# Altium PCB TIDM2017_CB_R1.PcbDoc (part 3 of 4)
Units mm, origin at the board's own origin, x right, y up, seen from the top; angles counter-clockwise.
Board outline 120 x 77 mm, 4 copper layers (Top Layer, Layer 1, Layer 2, Bottom Layer), stack 1.856 mm thick; 246 components, 167 nets, 1255 pads, 326 vias.
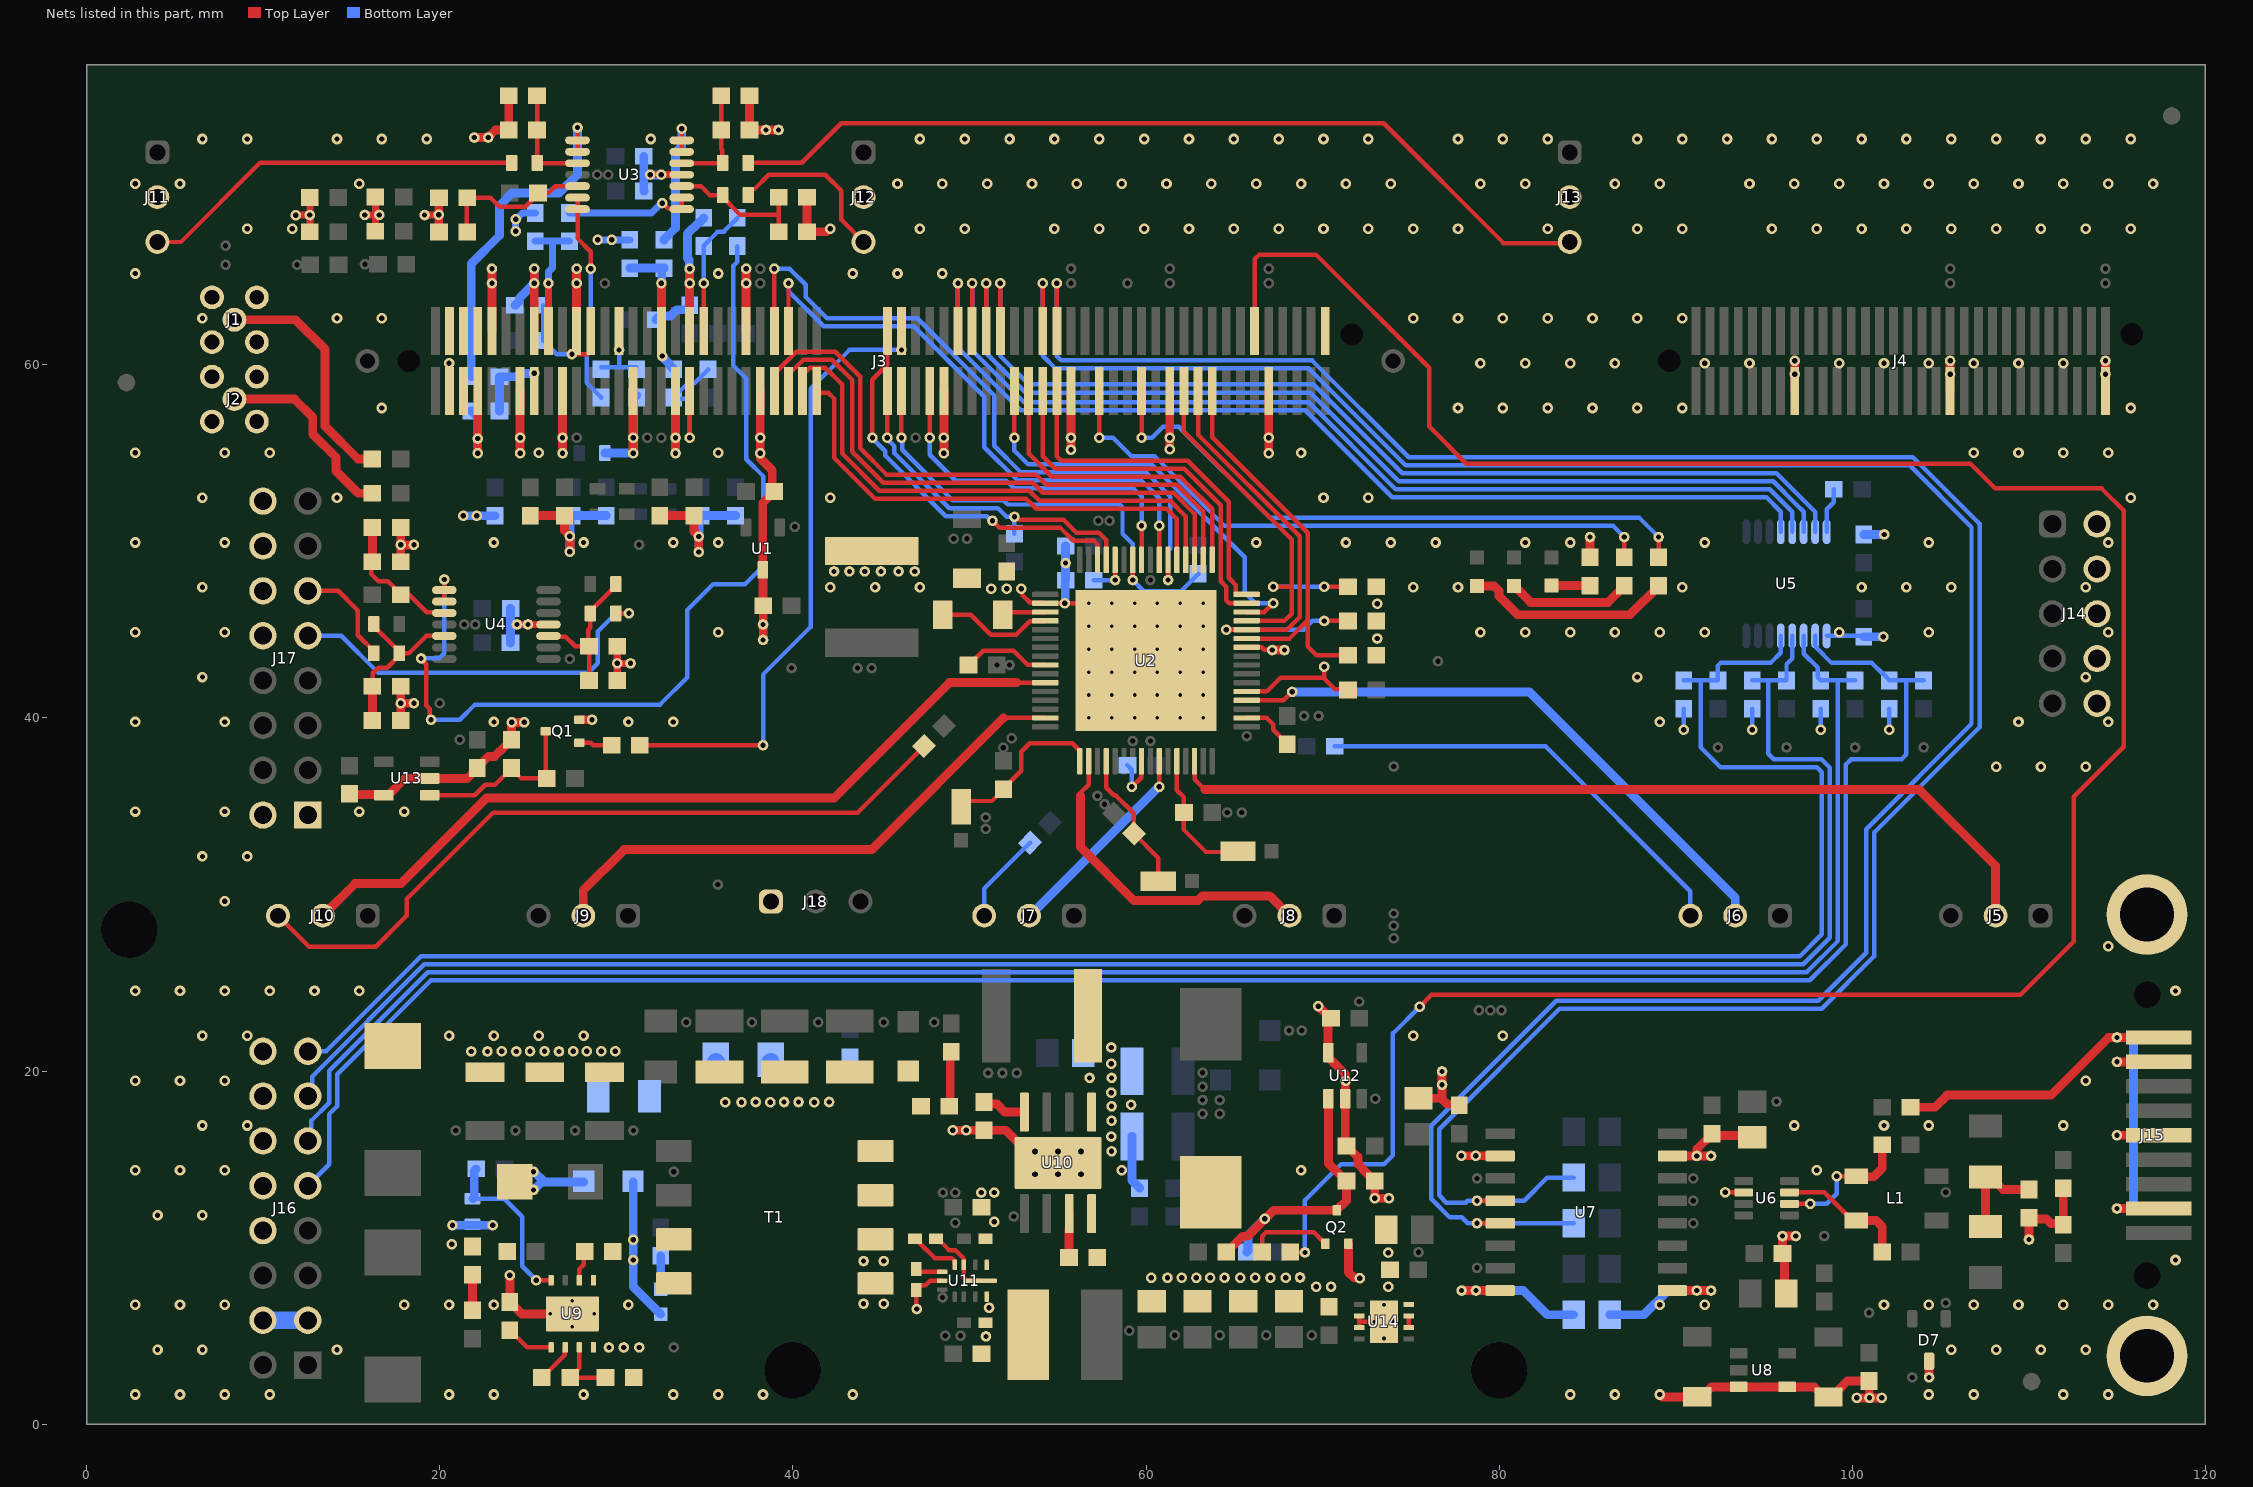
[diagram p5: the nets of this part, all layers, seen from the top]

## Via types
v1: diameter 0.6, hole 0.3, Top Layer to Bottom Layer, 276 vias
v2: diameter 0.5, hole 0.2, Top Layer to Bottom Layer, 40 vias
v3: diameter 0.63, hole 0.33, Top Layer to Bottom Layer, tented both sides, 6 vias
v4: diameter 0.5, hole 0.2, Top Layer to Bottom Layer, tented both sides, 4 vias

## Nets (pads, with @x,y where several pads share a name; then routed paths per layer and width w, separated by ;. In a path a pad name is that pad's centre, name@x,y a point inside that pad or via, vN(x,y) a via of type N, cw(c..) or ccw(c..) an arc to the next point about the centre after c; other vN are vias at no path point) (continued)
DRV_DRVOFF: J3.59 pad.2@46.15,55.875 pad.2@59.25,47.811 R11.1 U2.10 | length 27.1
  Top Layer w0.254: pad.2@46.15,55.875 J3.59@46.15,58.519 ; pad.2@59.25,47.811 U2.10@59.25,48.95
  Bottom Layer w0.254: pad.2@46.15,55.875 46.185,55.84 46.185,55.194 49.039,52.34 51.915,52.34 52.165,52.091 58.52,52.091 58.669,51.942 58.669,50.437 59.25,49.856 pad.2@59.25,47.811 59.877,47.184 61.986,47.184 62.95,48.148 R11.1@62.95,48.173
DRV_nASCIN: J3.63 pad.2@47.75,55.875 pad.2@59.75,50.884 U2.9 | length 20.2
  Top Layer w0.254: pad.2@47.75,55.875 J3.63@47.75,58.519 ; U2.9@59.75,48.95 pad.2@59.75,50.884
  Bottom Layer w0.254: pad.2@47.75,55.875 47.75,54.913 49.22,53.443 52.097,53.443 52.541,52.999 59.296,52.999 59.75,52.545 pad.2@59.75,50.884
DRV_nFLT1: J3.57 pad.2@45.35,55.875 pad.2@52.55,51.389 R21.2 U2.13 | length 19.8
  Top Layer w0.254: pad.2@45.35,55.875 J3.57@45.35,58.519 ; pad.2@52.55,51.389 52.644,51.389 52.817,51.216 55.341,51.216 56.059,50.498 57.333,50.498 57.75,50.081 U2.13@57.75,48.95
  Bottom Layer w0.254: pad.2@45.35,55.875 45.35,55.781 45.731,55.4 45.731,55.006 48.851,51.886 51.613,51.886 52.103,51.397 pad.2@52.542,51.397 ; R21.2@52.55,50.442 pad.2@52.55,51.389
DRV_nFLT2: pad.2@70.091,42.905 R22.2 U2.53 | length 7
  Top Layer w0.254: U2.53@65.7,41.5 66.845,41.5 67.62,42.275 70.054,42.275 ; pad.2@70.091,42.905 70.091,42.312 70.054,42.275 ; R22.2@71.439,41.587 71.403,41.622 70.706,41.622 70.054,42.275
DRV_nSLEEP: J3.58 pad.2@44.502,55.875 pad.2@51.305,51.17 U2.14 | length 22.7
  Top Layer w0.254: pad.2@44.502,55.875 44.502,59.156 45.35,60.004 J3.58@45.35,61.919 ; pad.2@51.305,51.17 51.712,50.762 55.153,50.762 55.871,50.044 57.058,50.044 57.25,49.852 U2.14@57.25,48.95
  Bottom Layer w0.254: pad.2@44.502,55.875 44.502,55.836 45.09,55.248 ; 45.091,55.248 45.24,55.099 45.24,54.855 48.663,51.432 50.983,51.432 51.246,51.17 pad.2@51.305,51.17
DRV_PHCA: J3.103 R14.2 U2.59 | length 23.6
  Top Layer w0.254: J3.103@63.75,58.55 63.75,55.892 69.156,50.486 69.156,45.528 ; U2.59@65.7,44.5 68.129,44.5 69.156,45.528 ; R14.2@71.091,43.899 R14.2@71.439,43.551 69.655,43.551 69.156,44.05 69.156,45.528
DRV_PHCB: J3.101 pad.2@64.55,45 pad.2@70.091,45.493 R19.2 U2.60 | length 26.8
  Top Layer w0.254: J3.101@62.95,58.55 62.95,56.05 68.702,50.298 68.702,45.716 67.987,45 U2.60@65.7,45 pad.2@64.55,45 ; pad.2@70.091,45.493 R19.2@71.439,45.493 R19.2@71.45,45.493
  Bottom Layer w0.254: pad.2@64.55,45 68.928,45 69.421,45.493 pad.2@70.091,45.493
DRV_PHCC: J3.99 pad.2@67.202,47.434 pad.2@70.091,47.434 R20.2 U2.61 | length 23.3
  Top Layer w0.254: J3.99@62.222,58.478 62.15,58.55 62.15,56.208 68.248,50.11 68.248,47.5 ; U2.61@65.7,45.5 67.845,45.5 68.248,45.904 68.248,47.5 ; pad.2@67.202,47.434 68.183,47.434 68.248,47.5 ; pad.2@70.091,47.434 R20.2@71.439,47.434
  Bottom Layer w0.254: pad.2@67.202,47.434 pad.2@70.091,47.434
DRV_PWM_AH: J3.49 U2.2 | length 34.6
  Top Layer w0.254: J3.49@38.95,58.55 38.95,59.504 40.196,60.75 42.392,60.75 43.813,59.329 43.813,55.269 45.296,53.785 53.767,53.785 54.347,53.205 54.48,53.205 ; 54.48,53.205 61.744,53.205 63.25,51.699 U2.2@63.25,48.95
DRV_PWM_AL: J3.51 U2.3 | length 32.9
  Top Layer w0.254: J3.51@39.75,58.55 39.75,59.45 40.596,60.296 42.204,60.296 43.359,59.141 43.359,55.08 45.108,53.331 53.579,53.331 54.159,52.751 61.555,52.751 62.75,51.556 U2.3@62.75,48.95
DRV_PWM_BH: J3.53 U2.4 | length 31
  Top Layer w0.254: J3.53@40.55,58.55 40.55,59.426 40.966,59.842 41.84,59.842 42.785,58.897 42.785,54.986 44.893,52.877 53.391,52.877 53.971,52.297 61.367,52.297 62.25,51.414 U2.4@62.25,48.95
DRV_PWM_BL: J3.55 U2.5 | length 27.7
  Top Layer w0.254: J3.55@41.35,58.519 41.451,58.418 42.003,58.418 42.331,58.09 42.331,54.746 44.654,52.423 53.203,52.423 53.584,52.042 53.783,51.843 61.179,51.843 61.75,51.272 U2.5@61.75,48.95
DRV_PWM_CH: J3.50 pad.2@38.95,65.45 pad.2@61.25,47.811 U2.6 | length 39.3
  Top Layer w0.254: J3.50@38.95,61.95 pad.2@38.95,65.45 ; pad.2@61.25,47.773 pad.2@61.25,47.811 U2.6@61.25,48.95
  Bottom Layer w0.254: pad.2@38.95,65.45 39.812,65.45 40.721,64.541 40.721,63.847 41.932,62.636 47.039,62.636 51.412,58.263 51.412,55.412 52.917,53.907 60.01,53.907 61.377,52.539 61.377,49.588 61.25,49.461 pad.2@61.25,47.811
DRV_PWM_CL: J3.52 pad.2@39.75,64.625 pad.2@60.75,50.884 U2.7 | length 34.1
  Top Layer w0.254: J3.52@39.75,61.95 pad.2@39.75,64.625 ; U2.7@60.75,48.95 pad.2@60.75,50.884
  Bottom Layer w0.254: pad.2@39.75,64.625 39.753,64.622 39.753,64.173 41.744,62.182 46.851,62.182 50.843,58.19 50.843,55.339 52.729,53.453 59.74,53.453 60.75,52.443 pad.2@60.75,50.884
DRV_SPI_CLK: J3.79 U2.63 | length 21.7
  Top Layer w0.254: J3.79@54.15,58.55 54.15,54.819 54.856,54.113 62.168,54.113 64.227,52.054 64.227,47.745 64.55,47.422 64.55,46.67 64.72,46.5 U2.63@65.7,46.5
DRV_SPI_CS: J3.81 U2.64 | length 21.1
  Top Layer w0.254: J3.81@54.95,58.55 54.95,54.81 55.193,54.567 62.356,54.567 64.681,52.242 64.681,47.933 65.083,47.531 65.083,47.023 65.106,47 U2.64@65.7,47 U2.64@66.3,47
DRV_SPI_SDI: J3.75 pad.2@52.55,55.875 pad.2@67.202,46.5 U2.62 | length 24.5
  Top Layer w0.254: pad.2@52.55,55.875 J3.75@52.55,58.55 ; U2.62@65.7,46 66.702,46 pad.2@67.202,46.5
  Bottom Layer w0.254: pad.2@52.55,55.875 52.55,55.135 53.325,54.361 60.32,54.361 65.586,49.094 65.586,47.114 66.2,46.5 pad.2@67.202,46.5
DRV_SPI_SDO: J3.77 U2.1 | length 18.2
  Top Layer w0.254: J3.77@53.35,58.427 53.35,54.977 54.668,53.659 61.932,53.659 62.406,53.184 62.408,53.184 63.75,51.842 U2.1@63.75,48.95 ; J3.77@53.35,58.55 J3.77@53.473,58.427
EN_POS_LDO: J3.110 pad.2@69.004,9.722 pad.2@75.501,23.644 R65.1 | length 144.4
  Top Layer w0.254: J3.110@66.15,61.919 66.15,65.975 66.425,66.25 69.625,66.25 76.04,59.835 76.04,56.509 78.144,54.405 106.701,54.405 108.106,53 114.125,53 115.375,51.75 115.375,38.364 112.552,35.541 112.552,27.335 109.532,24.315 76.172,24.315 pad.2@75.501,23.644 ; R65.1@68.18,9.75 68.208,9.722 pad.2@69.004,9.722
  Bottom Layer w0.254: pad.2@69.004,9.722 69.004,12.68 71.047,14.722 73.481,14.722 73.988,15.23 73.988,22.131 pad.2@75.501,23.644
EN_THROTTLE_LDO: J3.60 pad.2@38.308,38.45 pad.2@46.15,60.847 R63.1 | length 35.4
  Top Layer w0.254: R63.1@31.333,38.45 pad.2@38.308,38.45 ; pad.2@46.15,60.847 J3.60@46.15,61.919
  Bottom Layer w0.254: pad.2@38.308,38.45 38.308,42.458 41,45.15 41,58.646 43.201,60.847 pad.2@46.15,60.847
EQEP_A: C53.1 J16.15 R27.1 U5.13 | length 116.5
  Bottom Layer w0.254: J16.15@12.52,21.12 13.556,21.12 18.936,26.5 97.041,26.5 98.285,27.743 98.285,36.931 98.003,37.213 92.543,37.213 91.427,38.329 91.427,42.122 ; C53.1@90.456,42.122 91.427,42.122 ; U5.13@95.955,44.645 95.955,43.695 95.374,43.114 92.546,43.114 92.397,42.965 R27.1@92.397,42.122 91.427,42.122
EQEP_B: C17.1 J16.13 R23.1 U5.12 | length 112.7
  Bottom Layer w0.254: J16.13@12.52,18.58 12.768,18.828 12.768,19.69 19.124,26.046 97.229,26.046 98.739,27.555 98.739,37.189 98.261,37.667 95.551,37.667 95.246,37.971 95.246,42.059 95.31,42.122 ; C17.1@94.339,42.122 95.31,42.122 ; U5.12@96.605,44.645 96.605,43.363 96.28,43.038 R23.1@96.28,42.122 95.31,42.122
EQEP_I: C19.1 J16.9 R25.1 U5.10 | length 121.1
  Bottom Layer w0.254: J16.9@12.52,13.5 13.735,14.715 13.735,17.563 14.189,18.017 14.189,19.826 19.5,25.138 97.605,25.138 99.647,27.179 99.647,37.366 99.948,37.667 102.796,37.667 103.076,37.947 103.076,42.122 ; U5.10@97.905,44.645 97.905,44.117 98.003,44.019 98.003,43.941 98.831,43.114 101.113,43.114 101.732,42.495 101.757,42.495 102.105,42.147 C19.1@102.105,42.122 103.076,42.122 ; R25.1@104.046,42.122 103.076,42.122
EQEP_PWM: C18.1 J16.11 R24.1 U5.11 | length 112.6
  Bottom Layer w0.254: J16.11@12.52,16.04 12.728,16.248 12.728,17.199 13.735,18.205 13.735,20.015 19.312,25.592 97.417,25.592 99.193,27.367 99.193,42.122 ; U5.11@97.255,44.645 97.255,43.641 98.042,42.854 98.042,42.302 C18.1@98.222,42.122 99.193,42.122 ; R24.1@100.163,42.122 99.193,42.122
GHA: J10.2 U2.27 | length 46.4
  Top Layer w0.254: 52.663,42 U2.27@54.3,42
  Top Layer w0.5: J10.2@13.376,28.798 15.197,30.619 17.797,30.619 22.636,35.459 42.329,35.459 48.87,42 52.663,42
GHB: J7.2 pad.2@60.75,36.095 U2.42 | length 11.9
  Top Layer w0.254: pad.2@60.75,36.095 U2.42@60.75,37.55
  Bottom Layer w0.254: J7.2@53.376,28.798 J7.2@53.415,28.798 ; pad.2@60.711,36.095 pad.2@60.75,36.095
  Bottom Layer w0.5: J7.2@53.415,28.798 pad.2@60.711,36.095
GHC: J6.2 pad.2@68.279,41.477 U2.52 | length 33.7
  Top Layer w0.254: U2.52@65.7,41 67.793,41 68.27,41.477 pad.2@68.279,41.477
  Bottom Layer w0.5: pad.2@68.279,41.477 81.719,41.477 93.376,29.82 J6.2@93.376,28.798
GLA: J9.2 U2.31 | length 31.7
  Top Layer w0.254: 51.922,40 U2.31@54.3,40
  Top Layer w0.5: J9.2@28.126,28.798 28.126,30.236 30.436,32.545 44.467,32.545 51.922,40
GLB: J8.2 U2.34 | length 18.7
  Top Layer w0.254: 56.283,35.583 56.283,35.75 56.75,36.217 U2.34@56.75,37.55
  Top Layer w0.5: 56.283,35.583 56.283,32.695 59.316,29.662 62.937,29.662 63.198,29.923 67.001,29.923 J8.2@68.126,28.798
GLC: J5.2 U2.46 | length 50.8
  Top Layer w0.254: U2.46@62.75,37.55 62.75,36.528 63.338,35.94
  Top Layer w0.5: 63.338,35.94 103.802,35.94 108.126,31.616 J5.2@108.126,29.25
GND: C1.2 C2.1 C3.1 C4.2 C13.2 C14.2 C15.2 C16.1 C17.2 C18.2 C19.2 C20.1 C21.2 C22.2 C23.2 C24.2 C32.1 C37.2 C38.2 C39.2 C40.2 C48.1 C51.2 C52.2 C53.2 C54.1 C55.2 C56.1 C57.2 C58.2 C59.2 C60.2 C61.2 C62.2 C63.2 C64.2 C65.2 C66.2 C67.1 C68.2 C69.2 C70.2 C71.2 C72.2 C73.1 C74.2 C75.2 C76.2 C77.2 C78.1 C79.2 C80.1 C81.2 C82.1 C83.1 C84.1 C85.1 C86.1 C87.1 C88.2 C89.1 C90.2 C91.1 C92.1 C93.2 C94.1 C95.1 C96.2 J1.2 J1.3 J1.4 J1.5 J2.2 J2.3 J2.4 J2.5 J3.7 J3.10 J3.13 J3.16 J3.19 J3.22 J3.29 J3.35 J3.38 J3.46 J3.47 J3.65 J3.83 J3.97 J3.111 J4.135 J4.157 J4.179 J11.2 J12.2 J13.2 J14.2 J14.4 J14.6 J14.8 J14.10 J16.8 J16.10 J16.12 J16.14 J16.16 J17.1 J17.2 J17.10 J17.12 J17.14 J17.16 J18.1 pad.2@11.837,68.472 pad.2@12.638,68.487 pad.2@15.75,68.494 pad.2@16.572,68.494 pad.2@17.782,40.829 pad.2@17.782,49.804 pad.2@18.532,40.829 pad.2@18.532,49.804 pad.2@19.137,68.487 pad.2@19.937,68.501 pad.2@21.331,51.45 pad.2@21.956,72.877 pad.2@22.15,55 pad.2@22.15,55.825 pad.2@22.088,51.45 pad.2@22.95,64.625 pad.2@22.95,65.45 pad.2@22.744,72.877 pad.2@24.55,55 pad.2@24.55,55.875 pad.2@24.073,39.75 pad.2@24.297,67.568 pad.2@24.297,68.25 pad.2@24.371,45.294 pad.2@24.781,39.75 pad.2@24.992,45.294 pad.2@25.35,64.625 pad.2@25.35,65.45 pad.2@26.95,55 pad.2@26.95,55.875 pad.2@27.75,64.625 pad.2@27.75,65.45 pad.2@27.364,49.421 pad.2@27.364,50.296 pad.2@28.623,39.897 pad.2@28.948,67.081 pad.2@29.738,67.081 pad.2@30.05,43.091 pad.2@30.8,43.091 pad.2@30.95,55 pad.2@30.95,55.875 pad.2@31.92,70.776 pad.2@32.541,70.776 pad.2@32.602,60.498 pad.2@33.35,55 pad.2@33.35,55.875 pad.2@34.15,64.625 pad.2@34.15,65.45 pad.2@34.666,49.4 pad.2@34.666,50.275 pad.2@36.166,18.234 pad.2@37.35,64.625 pad.2@37.35,65.45 pad.2@37.085,18.234 pad.2@37.89,18.246 pad.2@38.15,55 pad.2@38.15,55.875 pad.2@38.308,44.419 pad.2@38.308,45.294 pad.2@38.475,73.305 pad.2@38.723,18.234 pad.2@39.183,73.305 pad.2@39.499,18.246 pad.2@40.32,18.246 pad.2@41.209,18.234 pad.2@42.05,18.246 pad.2@42.331,48.3 pad.2@43.201,48.3 pad.2@44,6.821 pad.2@44,9.237 pad.2@44.068,48.3 pad.2@44.985,48.3 pad.2@45.15,6.821 pad.2@45.15,9.237 pad.2@45.983,48.3 pad.2@46.901,48.3 pad.2@47.012,6.519 pad.2@48.55,55 pad.2@48.55,55.875 pad.2@49.058,16.646 pad.2@49.813,16.646 pad.2@50.665,13.115 pad.2@50.936,4.967 pad.2@51.108,6.586 pad.2@51.229,47.319 pad.2@51.402,11.458 pad.2@51.402,13.115 pad.2@52.106,47.319 pad.2@52.931,47.319 pad.2@55.75,55.194 pad.2@55.75,55.875 pad.2@55.402,46.5 pad.2@55.446,48.773 pad.2@56.804,19.61 pad.2@58.05,15.449 pad.2@58.05,17.179 pad.2@58.05,18 pad.2@58.05,19.61 pad.2@58.038,16.29 pad.2@58.038,18.777 pad.2@58.038,20.414 pad.2@58.038,21.334 pad.2@59.155,18.084 pad.2@60.297,8.284 pad.2@61.35,55.219 pad.2@61.35,55.875 pad.2@61.217,8.284 pad.2@62.021,8.296 pad.2@62.854,8.284 pad.2@63.631,8.296 pad.2@64.452,8.296 pad.2@65.341,8.284 pad.2@66.95,55 pad.2@66.95,55.875 pad.2@66.182,8.296 pad.2@67.049,8.293 pad.2@67.145,43.848 pad.2@67.845,43.848 pad.2@67.922,8.293 pad.2@68.727,8.305 pad.2@69.636,7.784 pad.2@69.758,23.676 pad.2@70.482,7.786 pad.2@72.114,8.269 pad.2@72.957,12.792 pad.2@73.102,44.5 pad.2@73.102,46.473 pad.2@73.717,9.715 pad.2@73.728,7.784 pad.2@73.763,12.792 pad.2@76.767,19.223 pad.2@76.769,19.975 pad.2@77.864,15.199 pad.2@77.876,7.568 pad.2@78.675,15.199 pad.2@78.687,7.568 pad.2@85.151,50.247 pad.2@90.456,39.329 pad.2@94.339,39.329 pad.2@96.748,59.472 pad.2@96.748,60.228 pad.2@98.222,39.329 pad.2@101.768,44.595 pad.2@101.823,50.395 pad.2@102.105,39.329 pad.2@105.548,59.472 pad.2@105.548,60.228 pad.2@114.348,59.472 pad.2@114.348,60.228 Q1.2 Q2.2 R2.1 R8.1 R14.1 R19.1 R20.1 R29.1 R32.1 R39.1 R45.1 R52.2 R54.1 R56.1 R59.1 R66.1 R69.1 R71.1 R73.1 R76.1 R78.1 R82.1 R84.1 R86.1 R87.1 T1.5 T1.6 U1.3 U2.18 U2.58 U2.65 U3.11 U4.11 U5.9 U7.2 U7.8 U10.1 U10.9 U11.1 U11.6 U11.11 U12.2 U12.5 U13.2 U13.5 U14.2 U14.3 U14.4 U14.6 U14.7 U14.9 | length 223
  Top Layer w0.254: pad.2@47.012,6.519 46.998,6.533 46.998,7.574 C96.2@46.984,7.588 46.984,7.688 47.157,7.861 47.511,7.861 47.771,8.121 U11.6@48.452,8.121 ; pad.2@52.931,47.319 52.997,47.253 52.997,46.969 53.444,46.523 54.277,46.523 U2.18@54.3,46.5 pad.2@55.402,46.5 v2(56.75,46.5) ; U2.58@65.7,44 66.556,44 66.702,43.854 67.139,43.854 pad.2@67.145,43.848 ; U14.7@72.081,5.474 72.081,5.799 ; U14.6@72.081,6.124 72.081,5.799 ; v4(72.931,5.799) 72.081,5.799 ; U14.2@74.881,5.474 U14.3@74.881,6.124
  Top Layer w0.4: pad.2@11.837,68.472 11.845,68.479 12.63,68.479 pad.2@12.638,68.487 ; R73.1@12.638,67.535 pad.2@12.638,68.487 ; C84.1@12.638,69.476 pad.2@12.638,68.487 ; pad.2@15.75,68.501 pad.2@16.347,68.496 ; C83.1@16.347,67.568 pad.2@16.347,68.496 ; R71.1@16.347,69.509 pad.2@16.347,68.496 ; pad.2@19.137,68.487 19.144,68.494 19.929,68.494 pad.2@19.937,68.501 ; pad.2@24.371,45.294 U4.11@26.155,45.294 ; C91.1@30.05,42.12 pad.2@30.05,43.091 ; R84.1@30.05,44.061 pad.2@30.05,43.091 ; pad.2@30.8,43.091 pad.2@30.05,43.091 ; pad.2@31.92,70.776 pad.2@32.541,70.776 32.544,70.773 33.695,70.773 U3.11@33.699,70.77
  Top Layer w0.5: C65.2@14.887,35.7 14.926,35.661 16.788,35.661 U13.5@16.827,35.623 17.077,35.623 18.027,36.573 U13.2@19.427,36.573 21.546,36.573 22.115,37.142 C64.2@22.115,37.167 22.115,37.192 22.74,37.817 23.095,37.817 23.395,38.117 23.406,38.117 C67.1@23.806,38.517 ; C82.1@17.782,39.858 pad.2@17.782,40.829 ; R69.1@17.782,41.8 pad.2@17.782,40.829 ; R66.1@17.782,48.844 pad.2@17.782,49.804 ; C80.1@17.782,50.785 pad.2@17.782,49.804 ; pad.2@18.532,40.829 pad.2@17.782,40.829 ; pad.2@18.532,49.804 pad.2@17.782,49.804 ; R8.1@19.937,67.53 pad.2@19.937,68.501 C78.1@19.937,69.472 ; pad.2@21.956,72.877 pad.2@22.744,72.877 22.744,72.896 23.153,73.305 C20.1@23.903,73.305 R32.1@23.903,75.246 ; pad.2@22.15,55 J3.7@22.15,58.519 J3.7@22.15,58.55 ; J3.10@22.95,61.95 pad.2@22.95,65.45 ; C67.1@24.056,38.767 24.065,38.775 24.065,39.742 pad.2@24.073,39.75 pad.2@24.781,39.75 ; pad.2@24.55,55 J3.13@24.55,58.519 J3.13@24.55,58.55 ; C85.1@25.128,51.46 R76.1@27.069,51.46 27.069,50.618 27.364,50.323 pad.2@27.364,50.296 pad.2@27.364,49.421 ; J3.16@25.35,61.95 pad.2@25.35,65.45 ; pad.2@26.95,55 J3.19@26.95,58.519 J3.19@26.95,58.55 ; J3.22@27.75,61.95 pad.2@27.75,65.45 ; Q1.2@27.9,39.9 27.901,39.899 28.621,39.899 pad.2@28.623,39.897 ; pad.2@30.95,55 J3.29@30.95,58.519 J3.29@30.95,58.55 ; R78.1@32.455,51.46 C86.1@34.397,51.46 34.397,50.57 34.666,50.302 pad.2@34.666,50.275 pad.2@34.666,49.4 ; pad.2@33.35,55 pad.2@33.35,55.875 33.35,56.676 J3.35@33.35,58.519 J3.35@33.35,58.55 ; J3.38@34.15,61.95 pad.2@34.15,65.45 ; J3.46@37.35,61.95 pad.2@37.35,65.45 ; R56.1@37.544,75.246 C56.1@37.544,73.305 pad.2@38.475,73.305 pad.2@39.183,73.305 ; J3.47@38.15,58.55 J3.47@38.15,58.519 pad.2@38.15,55.875 pad.2@38.15,55 38.15,54.707 38.832,54.025 38.832,52.908 38.941,52.8 38.916,52.8 38.294,52.178 U1.3@38.294,48.389 38.308,48.376 38.308,46.365 C1.2@38.322,46.351 38.315,46.345 38.315,44.426 pad.2@38.308,44.419 ; C54.1@40.797,69.5 R29.1@40.797,67.54 41.909,67.54 42.086,67.716 v1(42.113,67.716) ; pad.2@48.55,55 J3.65@48.55,58.519 J3.65@48.55,58.55 ; pad.2@49.058,16.646 pad.2@49.813,16.646 R54.1@50.827,16.646 52.052,16.646 52.674,16.024 53.14,16.024 v3(53.715,15.449) ; pad.2@55.75,55.194 J3.83@55.75,58.519 J3.83@55.75,58.55 ; pad.2@61.35,55.219 J3.97@61.35,58.519 J3.97@61.35,58.55 ; pad.2@66.95,55 J3.111@66.95,58.519 J3.111@66.95,58.55 ; pad.2@67.145,43.848 pad.2@67.845,43.848 ; pad.2@69.758,23.676 69.766,23.676 70.311,23.13 70.311,21.055 U12.5@70.332,21.035 70.332,20.785 71.282,19.835 U12.2@71.282,18.435 71.282,15.822 C68.2@71.357,15.747 71.382,15.747 72.007,15.122 72.007,14.738 72.307,14.438 72.307,14.402 72.932,13.777 C73.1@72.957,13.777 pad.2@72.957,12.792 pad.2@73.763,12.792 ; C70.2@70.361,6.615 C70.2@70.361,6.64 ; Q2.2@71.461,10.214 71.461,8.611 71.785,8.288 72.094,8.288 pad.2@72.114,8.269 ; C23.2@75.432,18.46 76.767,18.46 76.769,18.462 ; pad.2@76.769,19.975 76.769,18.462 ; C24.2@77.75,18.08 C24.2@77.75,18.055 77.686,18.119 77.057,18.119 76.769,18.407 76.769,18.462 ; pad.2@77.864,15.199 pad.2@78.675,15.199 U7.2@80.054,15.199 ; pad.2@77.876,7.568 pad.2@78.687,7.568 U7.8@80.066,7.568 ; R2.1@85.15,49.095 pad.2@85.151,50.247 ; J4.135@96.748,58.528 pad.2@96.748,59.472 pad.2@96.748,60.228 ; J4.157@105.548,58.528 pad.2@105.548,59.472 pad.2@105.548,60.228 ; J4.179@114.348,58.528 pad.2@114.348,59.472 pad.2@114.348,60.228
  Bottom Layer w0.254: pad.2@90.456,39.329 C53.2@90.456,40.522 ; pad.2@94.339,39.329 C17.2@94.339,40.522 ; pad.2@98.222,39.329 C18.2@98.222,40.522 ; U5.9@98.555,44.645 100.607,44.645 C16.1@100.657,44.595 ; pad.2@102.105,39.329 C19.2@102.105,40.522
  Bottom Layer w0.4: 24.007,45.226 24.075,45.294 pad.2@24.371,45.294 pad.2@24.992,45.294 ; pad.2@24.297,67.568 pad.2@24.297,68.25 24.326,68.25 24.68,68.604 C22.2@25.405,68.604 ; pad.2@28.948,67.081 C55.2@30.76,67.081 ; C93.2@31.549,71.823 C93.2@31.554,71.818
  Bottom Layer w0.5: pad.2@21.331,51.45 C32.1@23.125,51.45 ; C21.2@21.78,57.385 21.805,57.385 22.03,57.16 22.03,57.135 22.15,57.015 pad.2@22.15,55 ; C87.1@24.005,44.254 24.007,44.257 24.007,45.226 ; 24.007,45.294 24.007,46.195 C88.2@24.01,46.197 ; C90.2@24.353,63.475 C90.2@24.253,63.375 24.278,63.375 24.503,63.6 24.503,63.778 pad.2@25.35,64.625 pad.2@25.35,65.45 ; pad.2@27.364,49.421 pad.2@27.364,50.296 27.384,50.315 27.384,51.363 C89.1@27.481,51.46 R82.1@29.423,51.46 ; R39.1@29.35,55 pad.2@30.95,55 30.969,55.019 30.969,58.086 C77.2@31.139,58.256 ; C93.2@31.554,71.818 31.554,69.859 C92.1@31.56,69.854 ; pad.2@31.733,70.757 32.522,70.757 pad.2@32.541,70.776 ; R87.1@32.232,62.557 32.438,62.762 33.062,62.762 33.425,63.125 33.925,63.125 34.15,63.35 C95.1@34.15,63.375 pad.2@34.15,64.625 pad.2@34.15,65.45 34.131,65.469 34.131,65.938 34.025,66.044 34.025,67.417 34.689,68.08 34.725,68.08 34.95,68.305 C79.2@34.95,68.33 ; pad.2@32.602,60.498 32.602,60.471 33.028,60.045 33.028,59.973 C81.2@33.253,59.748 ; pad.2@34.666,49.4 pad.2@34.666,50.275 34.685,50.294 34.685,51.336 R86.1@34.809,51.46 C94.1@36.75,51.46 ; pad.2@55.402,46.5 55.421,46.519 55.421,47.778 C4.2@55.446,47.802 pad.2@55.446,48.773 C76.2@55.446,49.744 ; C52.2@59.2,16.29 59.2,13.82 59.634,13.386 R59.1@59.634,13.361 ; pad.2@77.876,7.568 pad.2@78.687,7.568 81.367,7.568 82.737,6.198 R45.1@84.234,6.198 ; C16.1@100.657,44.595 pad.2@101.768,44.595 ; C15.2@100.657,50.395 pad.2@101.823,50.395
  Bottom Layer w1: J16.8@9.831,10.96 J16.8@9.98,10.96 ; C48.1@38.691,20.46 C48.1@38.741,20.51
  other v1: 4.013,11.836 6.553,11.836 2.743,14.376 5.283,14.376 7.823,14.376 58.623,14.376 68.783,14.376 6.553,16.916 9.093,16.916 2.743,19.456 5.283,19.456 7.823,19.456 71.323,19.456 6.553,21.996 9.093,21.996 75.133,21.996 80.213,21.996 2.743,24.536 5.283,24.536 7.823,24.536 10.363,24.536 12.903,24.536 15.443,24.536 7.823,29.616 6.553,32.156 9.093,32.156 2.743,34.696 7.823,34.696 15.443,34.696 17.983,34.696 108.153,37.236 110.693,37.236 113.233,37.236 2.743,39.776 7.823,39.776 23.063,39.776 30.683,39.776 33.223,39.776 89.103,39.776 109.423,39.776 114.503,39.776 6.553,42.316 87.833,42.316 113.233,42.316 2.743,44.856 7.823,44.856 35.763,44.856 78.943,44.856 81.483,44.856 84.023,44.856 86.563,44.856 89.103,44.856 91.643,44.856 99.263,44.856 104.343,44.856 114.503,44.856 6.553,47.396 42.113,47.396 44.653,47.396 47.193,47.396 75.133,47.396 77.673,47.396 90.373,47.396 100.533,47.396 103.073,47.396 105.613,47.396 113.233,47.396 2.743,49.936 7.823,49.936 23.063,49.936 28.143,49.936 33.223,49.936 35.763,49.936 66.243,49.936 71.323,49.936 73.863,49.936 76.403,49.936 81.483,49.936 84.023,49.936 91.643,49.936 104.343,49.936 114.503,49.936 6.553,52.476 14.173,52.476 42.113,52.476 70.053,52.476 72.593,52.476 115.773,52.476 2.743,55.016 7.823,55.016 10.363,55.016 25.603,55.016 35.763,55.016 68.783,55.016 106.883,55.016 109.423,55.016 111.963,55.016 114.503,55.016 16.713,57.556 77.673,57.556 80.213,57.556 82.753,57.556 85.293,57.556 87.833,57.556 90.373,57.556 115.773,57.556 20.523,60.096 78.943,60.096 81.483,60.096 84.023,60.096 86.563,60.096 91.643,60.096 94.183,60.096 99.263,60.096 101.803,60.096 104.343,60.096 106.883,60.096 109.423,60.096 111.963,60.096 6.553,62.636 14.173,62.636 16.713,62.636 75.133,62.636 77.673,62.636 80.213,62.636 82.753,62.636 85.293,62.636 87.833,62.636 90.373,62.636 2.743,65.176 35.763,65.176 43.383,65.176 45.923,65.176 48.463,65.176 9.093,67.716 11.633,67.716 47.193,67.716 49.733,67.716 54.813,67.716 57.353,67.716 59.893,67.716 62.433,67.716 64.973,67.716 67.513,67.716 70.053,67.716 72.593,67.716 75.133,67.716 77.673,67.716 82.753,67.716 87.833,67.716 90.373,67.716 95.453,67.716 97.993,67.716 100.533,67.716 103.073,67.716 105.613,67.716 108.153,67.716 110.693,67.716 113.233,67.716 115.773,67.716 2.743,70.256 5.283,70.256 15.443,70.256 45.923,70.256 48.463,70.256 51.003,70.256 53.543,70.256 56.083,70.256 58.623,70.256 61.163,70.256 63.703,70.256 66.243,70.256 68.783,70.256 71.323,70.256 73.863,70.256 78.943,70.256 81.483,70.256 86.563,70.256 89.103,70.256 94.183,70.256 96.723,70.256 99.263,70.256 101.803,70.256 104.343,70.256 106.883,70.256 109.423,70.256 111.963,70.256 114.503,70.256 117.043,70.256 6.553,72.796 9.093,72.796 14.173,72.796 16.713,72.796 19.253,72.796 31.953,72.796 47.193,72.796 49.733,72.796 52.273,72.796 54.813,72.796 57.353,72.796 59.893,72.796 62.433,72.796 64.973,72.796 67.513,72.796 70.053,72.796 72.593,72.796 77.673,72.796 80.213,72.796 82.753,72.796 87.833,72.796 90.373,72.796 92.913,72.796 95.453,72.796 97.993,72.796 100.533,72.796 103.073,72.796 105.613,72.796 108.153,72.796 110.693,72.796 113.233,72.796 115.773,72.796
  other v2: 56.75,40 58.05,40 59.35,40 60.65,40 61.95,40 63.25,40 56.75,41.3 58.05,41.3 59.35,41.3 60.65,41.3 61.95,41.3 63.25,41.3 56.75,42.6 58.05,42.6 59.35,42.6 60.65,42.6 61.95,42.6 63.25,42.6 56.75,43.9 58.05,43.9 59.35,43.9 60.65,43.9 61.95,43.9 63.25,43.9 56.75,45.2 58.05,45.2 59.35,45.2 60.65,45.2 61.95,45.2 63.25,45.2 58.05,46.5 59.35,46.5 60.65,46.5 61.95,46.5 63.25,46.5
  other v3: 53.715,14.149 55.015,14.149 56.315,14.149 55.015,15.449 56.315,15.449
  other v4: 73.481,4.849 74.031,5.799 73.481,6.749
GND_BATT: C25.2 C26.2 C27.2 C28.2 C29.2 C30.1 C31.1 C33.2 C34.2 C35.2 C42.1 C43.1 C44.1 C45.2 C47.2 C48.2 C49.2 D7.3 D11.2 J15.3 J15.6 J15.10 J15.11 J16.3 J16.4 pad.2@20.678,10.192 pad.2@20.713,11.267 pad.2@21.778,21.108 pad.2@22.697,21.108 pad.2@22.992,11.267 pad.2@23.501,21.12 pad.2@23.966,8.436 pad.2@24.335,21.108 pad.2@25.111,21.12 pad.2@25.932,21.12 pad.2@26.75,21.109 pad.2@27.552,21.12 pad.2@28.322,21.12 pad.2@29.14,21.12 pad.2@29.577,4.342 pad.2@29.942,21.12 pad.2@30.424,4.342 pad.2@31.295,4.346 pad.2@91.195,7.568 pad.2@91.195,15.188 pad.2@92.006,7.568 pad.2@92.006,15.188 pad.2@92.806,13.127 pad.2@96.052,10.653 pad.2@96.802,10.653 pad.2@100.264,1.486 pad.2@100.981,1.486 pad.2@101.68,1.486 pad.2@104.355,2.646 pad.2@110.016,10.456 pad.2@115,16.365 pad.2@115,20.518 R45.2 R52.1 R53.1 R58.1 U6.2 U7.9 U7.15 U8.3 U8.4 U9.8 U9.9@27.504,6.246 | length 55.1
  Top Layer w0.254: R53.1@30.961,2.64 R53.1@30.986,2.64 ; pad.2@92.806,13.127 U6.2@93.851,13.127
  Top Layer w0.5: pad.2@23.966,8.436 C49.2@23.966,6.919 23.966,6.894 24.191,6.669 24.216,6.669 24.639,6.246 v2(26.254,6.246) ; v1@89.122,1.657 89.149,1.657 89.262,1.545 91.474,1.545 92.038,2.109 U8.3@93.567,2.109 U8.4@96.317,2.109 97.837,2.109 98.41,1.536 C35.2@98.66,1.536 98.91,1.536 99.21,1.836 99.21,1.925 99.73,2.445 C34.2@100.955,2.445 100.968,2.432 100.968,1.5 pad.2@100.981,1.486 ; U7.9@89.816,7.568 pad.2@91.195,7.568 pad.2@92.006,7.568 ; U7.15@89.816,15.188 pad.2@91.195,15.188 ; pad.2@92.006,15.188 pad.2@91.195,15.188 ; C25.2@94.344,16.239 94.236,16.347 92.167,16.347 C26.2@92.059,16.455 92.059,16.43 91.214,15.585 91.214,15.207 pad.2@91.195,15.188 ; C27.2@96.268,7.4 96.16,7.508 96.16,9.557 C28.2@96.052,9.665 pad.2@96.052,10.653 pad.2@96.802,10.653 ; pad.2@100.264,1.486 pad.2@100.981,1.486 ; pad.2@101.68,1.486 pad.2@100.981,1.486 ; pad.2@104.355,2.646 D7.3@104.355,3.564 ; pad.2@110.016,10.456 C30.1@110.016,11.688 110.08,11.624 110.996,11.624 111.265,11.355 111.894,11.355 C29.2@111.958,11.292 C31.1@111.958,13.361 ; pad.2@115,16.365 J15.3@117.366,16.365 ; pad.2@115,20.518 J15.6@117.366,20.518
  Bottom Layer w0.5: pad.2@20.713,11.267 pad.2@22.992,11.267 ; R45.2@86.266,6.198 88.204,6.198 89.574,7.568 pad.2@91.195,7.568 pad.2@92.006,7.568
  Bottom Layer w1: J16.4@9.98,5.88 J16.3@12.52,5.88 ; C48.2@35.641,20.51 C48.2@35.691,20.46
  other v1: 2.743,1.676 5.283,1.676 7.823,1.676 10.363,1.676 20.523,1.676 23.063,1.676 28.143,1.676 33.223,1.676 35.763,1.676 38.303,1.676 43.383,1.676 84.023,1.676 86.563,1.676 89.103,1.676 104.343,1.676 106.883,1.676 111.963,1.676 114.503,1.676 4.013,4.216 6.553,4.216 14.173,4.216 105.613,4.216 108.153,4.216 110.693,4.216 113.233,4.216 2.743,6.756 5.283,6.756 7.823,6.756 17.983,6.756 20.523,6.756 23.063,6.756 30.683,6.756 89.103,6.756 91.643,6.756 101.803,6.756 104.343,6.756 106.883,6.756 109.423,6.756 111.963,6.756 114.503,6.756 117.043,6.756 118.313,9.296 97.993,14.376 96.723,16.916 101.803,16.916 104.343,16.916 111.963,16.916 113.233,19.456 20.523,21.996 23.063,21.996 25.603,21.996 28.143,21.996 118.313,24.536 114.503,27.076
  other v2: 27.504,5.506 28.754,6.246 27.504,6.986
ILEM_A_MCU: C21.1 J3.15 pad.2@25.35,59.531 R30.2 | length 5
  Top Layer w0.254: J3.15@25.35,58.519 pad.2@25.35,59.531
  Bottom Layer w0.5: C21.1@23.38,57.385 23.38,59.328 24.353,59.328 24.537,59.512 25.331,59.512 pad.2@25.35,59.531
ILEM_B_MCU: C22.1 J3.18 pad.2@26.15,64.625 R15.2 | length 7.1
  Top Layer w0.4: J3.18@26.15,61.919 pad.2@26.15,64.625
  Bottom Layer w0.4: C22.1@25.405,67.004 26.378,67.004 ; pad.2@26.15,64.625 26.15,65.275 26.378,65.503 26.378,67.004 ; R15.2@27.349,67.004 26.378,67.004
ILEM_C_MCU: C55.1 J3.34 pad.2@32.55,64.625 R31.2 | length 5.6
  Top Layer w0.5: J3.34@32.55,61.919 pad.2@32.55,64.625
  Bottom Layer w0.5: C55.1@30.76,65.481 R31.2@32.703,65.481 32.569,65.347 32.569,64.644 pad.2@32.55,64.625
INV_TEMP: J17.9 pad.2@30.711,45.925 R83.1 | length 22.2
  Top Layer w0.254: R83.1@29.975,45.925 pad.2@30.711,45.925
  Bottom Layer w0.254: J17.9@12.52,44.66 14.414,44.66 16.5,42.574 28.431,42.574 28.948,43.091 28.948,44.897 29.975,45.925 pad.2@30.711,45.925
IPH_U_IN: J11.3 R13.1 | length 21.9
  Top Layer w0.254: J11.3@4,66.96 5.335,66.96 9.815,71.44 R13.1@24.062,71.44
IPH_V_IN: J12.3 R28.1 | length 9.6
  Top Layer w0.254: R28.1@37.469,69.615 37.469,69.74 37.667,69.938 37.792,69.938 38.625,70.77 41.831,70.77 42.747,69.854 42.747,68.213 J12.3@44,66.96
IPH_W_IN: J13.3 R55.1 | length 50.7
  Top Layer w0.254: R55.1@37.469,71.44 40.501,71.44 42.746,73.686 73.46,73.686 80.247,66.898 83.938,66.898 J13.3@84,66.96 J13.3@84.38,66.96
LED-1: J3.87 pad.2@57.35,55.875 pad.2@87.091,50.247 R5.1 | length 35.9
  Top Layer w0.254: pad.2@57.35,55.875 J3.87@57.35,58.519 ; R5.1@87.091,49.095 pad.2@87.091,50.247
  Bottom Layer w0.254: pad.2@57.35,55.875 58.133,55.875 59.194,54.815 60.508,54.815 64.448,50.874 86.464,50.874 pad.2@87.091,50.247
LED-2: J3.93 pad.2@59.75,55.875 pad.2@89.035,50.247 R3.1 | length 35.9
  Top Layer w0.254: pad.2@59.75,55.875 J3.93@59.75,58.519 ; R3.1@89.035,49.095 pad.2@89.035,50.247
  Bottom Layer w0.254: pad.2@59.75,55.875 60.336,55.875 60.963,56.502 61.856,56.502 67.03,51.328 87.954,51.328 pad.2@89.035,50.247
MCAN_RX: J3.80 pad.2@54.15,64.625 pad.2@78.75,11.378 R42.1 U7.5 | length 132.8
  Top Layer w0.254: J3.80@54.15,61.919 pad.2@54.15,64.625 ; pad.2@78.75,11.378 U7.5@80.066,11.378
  Bottom Layer w0.254: pad.2@54.15,64.625 54.15,60.521 54.875,59.796 69.215,59.796 74.7,54.311 103.254,54.311 106.76,50.805 106.76,39.663 100.801,33.704 100.801,26.701 98.083,23.984 83.237,23.984 76.149,16.897 76.149,12.77 77.195,11.724 77.879,11.724 78.225,11.378 pad.2@78.75,11.378 R42.1@84.234,11.378
MCAN_TX: J3.82 pad.2@54.95,64.625 pad.2@78.75,12.648 R43.1 U7.4 | length 132.2
  Top Layer w0.254: J3.82@54.95,61.919 pad.2@54.95,64.625 ; pad.2@78.75,12.648 U7.4@80.066,12.648
  Bottom Layer w0.254: pad.2@54.95,64.625 54.95,60.5 55.2,60.25 69.404,60.25 74.888,54.765 103.442,54.765 103.896,54.311 107.214,50.993 107.214,39.475 101.255,33.516 101.255,26.513 98.271,23.53 83.425,23.53 76.603,16.708 76.603,12.958 77.016,12.545 78.105,12.545 78.208,12.648 81.417,12.648 82.737,13.968 R43.1@84.234,13.968
MCU_INV_TEMP: C90.1 J3.24 pad.2@27.481,60.608 R81.2 | length 6.2
  Top Layer w0.254: pad.2@27.481,60.608 28.387,60.608 28.55,60.771 J3.24@28.55,61.919
  Bottom Layer w0.254: C90.1@25.853,63.375 R81.2@25.853,61.375 25.878,61.375 26.226,61.027 26.226,61.002 26.62,60.608 pad.2@27.481,60.608
MCU_MOTOR_TEMP: C81.1 J3.37 pad.2@34.15,55.875 R67.2 | length 8.3
  Top Layer w0.254: pad.2@34.15,55.875 J3.37@34.15,58.519
  Bottom Layer w0.254: pad.2@34.15,55.875 34.15,57.937 34.001,58.086 33.314,58.086 C81.1@33.253,58.148 33.253,58.173 34.028,58.948 34.419,58.948 35.194,59.723 R67.2@35.194,59.748
MCU_QEP_A: J3.68 pad.2@49.35,64.625 U5.4 | length 57.9
  Top Layer w0.254: J3.68@49.35,61.95 pad.2@49.35,64.625
  Bottom Layer w0.254: pad.2@49.35,64.625 49.35,60.967 52.442,57.875 52.452,57.875 52.906,57.421 69.022,57.421 73.948,52.495 95.148,52.495 95.955,51.687 U5.4@95.955,50.545
MCU_QEP_B: J3.70 pad.2@50.15,64.625 U5.5 | length 57.9
  Top Layer w0.254: J3.70@50.15,61.95 pad.2@50.15,64.625
  Bottom Layer w0.254: pad.2@50.15,64.625 50.15,60.819 53.094,57.875 69.21,57.875 74.136,52.949 95.336,52.949 96.605,51.679 U5.5@96.605,50.545
MCU_QEP_I: J3.74 pad.2@51.75,64.625 U5.7 | length 57.7
  Top Layer w0.254: J3.74@51.75,61.95 pad.2@51.75,64.625
  Bottom Layer w0.254: pad.2@51.75,64.625 51.75,60.503 53.356,58.897 69.473,58.897 74.512,53.857 95.712,53.857 97.905,51.663 U5.7@97.905,50.545
MCU_QEP_PWM: J3.72 pad.2@50.95,64.625 U5.6 | length 57.8
  Top Layer w0.254: J3.72@50.95,61.95 pad.2@50.95,64.625
  Bottom Layer w0.254: pad.2@50.95,64.625 50.95,60.661 53.193,58.418 69.309,58.418 74.324,53.403 95.524,53.403 96.863,52.063 97.255,51.672 U5.6@97.255,50.545
MCU_TCK: J3.5
MCU_TDI: J3.8
MCU_TDO: J3.6
MCU_THROTTLE_1: C77.1 J3.28 pad.2@30.151,60.847 R6.2 | length 4.1
  Top Layer w0.254: J3.28@30.151,60.847 J3.28@30.15,61.919
  Bottom Layer w0.254: R6.2@29.13,59.858 30.134,59.858 ; pad.2@30.151,60.847 30.151,59.876 30.134,59.858 ; C77.1@31.139,59.856 31.137,59.858 30.134,59.858
MCU_THROTTLE_2: C79.1 J3.40 pad.2@34.95,64.625 R9.2 | length 7.4
  Top Layer w0.254: J3.40@34.95,61.919 pad.2@34.95,64.625
  Bottom Layer w0.254: pad.2@34.95,64.625 C79.1@34.95,66.73 34.95,66.755 35.725,67.53 36.119,67.53 36.119,67.58 36.844,68.305 R9.2@36.844,68.33
MCU_TMS: J3.3
MCU_TRSTn: J3.4
MCU_XRSn: J3.120
MOTOR_TEMP: J17.11 R68.1 | length 6.1
  Top Layer w0.254: J17.11@12.52,47.2 14.24,47.2 15.358,46.082 15.358,44.686 16.257,43.788 R68.1@16.257,43.663
NetC4_1: C4.1 pad.2@58.25,47.811 U2.12 | length 2.3
  Top Layer w0.254: pad.2@58.25,47.811 U2.12@58.25,48.95
  Bottom Layer w0.254: C4.1@57.046,47.811 pad.2@58.25,47.811
NetC5_2: C5.2 U2.25 | length 5
  Top Layer w0.254: C5.2@49.95,43 49.975,43 50.777,43.802 52.496,43.802 53.298,43 U2.25@54.3,43 U2.25@54.277,43.023
NetC6_2: C6.2 D4.1 U2.33 | length 9.6
  Top Layer w0.254: D4.1@49.527,34.971 49.852,35.296 51.275,35.296 51.922,35.942 51.922,35.992 52.931,37.001 52.931,38.078 53.423,38.57 55.83,38.57 56.25,38.15 U2.33@56.25,37.55
NetC7_1: C7.1 U2.20 | length 6.6
  Top Layer w0.254: C7.1@48.482,45.839 50.07,45.839 51.198,44.71 52.641,44.71 53.415,45.484 54.284,45.484 U2.20@54.3,45.5
NetC7_2: C7.2 U2.19 | length 3
  Top Layer w0.254: C7.2@51.447,46.354 C7.2@51.801,46 ; C7.2@51.882,45.839 52.043,46 U2.19@54.3,46 ; C7.2@51.882,46.334 C7.2@51.895,46.322
NetC8_2: C8.2 pad.2@59.2,36.095 U2.40 | length 3
  Top Layer w0.254: pad.2@59.2,36.095 59.727,36.622 59.727,37.527 U2.40@59.75,37.55
  Bottom Layer w0.254: C8.2@58.95,37.321 59.2,37.071 pad.2@59.2,36.095
NetC9_2: C9.2 D5.1 U2.36 | length 8.1
  Top Layer w0.254: U2.36@57.773,37.527 U2.36@57.75,37.55 57.75,36.041 58.167,35.625 58.276,35.625 59.298,34.602 59.298,33.468 C9.2@59.316,33.45 60.699,32.067 D5.1@60.699,30.76
NetC10_2: C10.2 U2.50 | length 3.1
  Top Layer w0.254: U2.50@65.7,40 66.831,40 67.202,39.629 67.202,39.338 68.004,38.536 C10.2@68.004,38.511
NetC11_2: C11.2 D6.1 U2.44 | length 7.6
  Top Layer w0.254: U2.44@61.75,37.55 61.75,35.907 62.15,35.507 C11.2@62.15,34.642 62.15,33.656 63.399,32.407 65.126,32.407 D6.1@65.169,32.45
NetC12_1: C12.1 L3.1 U11.3 U11.12 | length 4.1
  Top Layer w0.254: C12.1@48.112,10.489 48.212,10.489 48.385,10.316 48.385,10.313 48.836,9.862 49.194,9.862 49.677,9.38 49.677,8.301 49.857,8.121 U11.12@50.64,8.121
NetC12_2: C12.2 U11.4 | length 3
  Top Layer w0.254: C12.2@46.912,10.489 47.012,10.489 47.185,10.316 47.185,10.254 48.031,9.408 49.006,9.408 49.177,9.238 U11.4@49.177,9.021
NetC20_2: C20.2 R13.2 R32.2 U3.3 | length 6.3
  Top Layer w0.254: R32.2@25.503,75.246 25.512,75.237 R13.2@25.512,71.44 25.532,71.42 U3.3@27.799,71.42 U3.3@28,71.42
NetC30_2: C30.2 R35.1 R36.2 | length 5.6
  Top Layer w0.5: R35.1@107.556,11.2 R36.2@107.556,13.999 107.831,13.999 108.541,13.288 C30.2@110.016,13.288
NetC36_1: C36.1 R46.1 | length 3.1
  Top Layer w0.5: C36.1@48.853,18 48.912,18.058 48.912,21.035 R46.1@48.97,21.094
NetC36_2: C36.2 D8.2 T1.7 T1.8
NetC41_2: C41.2 C45.1 | length 2
  Top Layer w0.5: C41.2@21.847,6.444 C45.1@21.847,8.461
NetC46_1: C46.1 R47.1 | length 1.9
  Bottom Layer w0.5: C46.1@32.511,7.65 R47.1@32.511,9.541
NetC46_2: C46.2 D13.2 pad.2@30.954,9.295 pad.2@30.954,10.438 R51.2 T1.3 T1.4 U9.1 | length 8.2
  Top Layer w0.254: R51.2@29.75,9.736 R51.2@29.8,9.786
  Bottom Layer w0.5: D13.2@30.954,13.723 pad.2@30.954,9.295 30.954,7.784 C46.2@32.511,6.227
NetC49_1: C49.1 U9.5 | length 2.8
  Top Layer w0.254: C49.1@23.966,5.319 23.966,5.294 24.314,4.946 24.339,4.946 24.939,4.346 U9.5@26.304,4.346
NetC50_1: C50.1 U10.7 | length 2.5
  Top Layer w0.5: C50.1@55.636,9.434 55.636,11.06 55.65,11.074 U10.7@55.65,11.924
NetC50_2: C50.2 L2.1 U10.8 | length 0.1
  Top Layer w0.5: C50.2@57.236,9.434 C50.2@57.3,9.498
NetC54_2: C54.2 R28.2 R29.2 U3.10 | length 8.2
  Top Layer w0.254: U3.10@33.699,70.12 34.794,70.12 35.299,69.615 R28.2@36.019,69.615 36.019,69.49 36.993,68.516 39.197,68.516 ; R29.2@39.197,67.54 39.197,68.516 ; C54.2@39.197,69.5 39.197,68.516
NetC56_2: C56.2 R55.2 R56.2 U3.12 | length 6.2
  Top Layer w0.254: U3.12@33.699,71.42 35.999,71.42 R55.2@36.019,71.44 35.999,71.46 35.999,72.193 35.944,72.248 C56.2@35.944,73.305 R56.2@35.944,75.246
NetC67_2: C67.2 Q1.3 R62.2 U13.1 | length 10.2
  Top Layer w0.254: U13.1@19.427,35.623 21.984,35.623 22.57,36.208 23.123,36.208 24.056,37.142 24.625,36.573 R62.2@26.053,36.573 26,36.625 Q1.3@26,39.25
NetC73_2: C73.2 pad.2@66.724,11.632 Q2.3 R64.2 R88.2 U12.1 | length 17
  Top Layer w0.254: R64.2@64.554,9.75 R64.2@64.902,10.098
  Top Layer w0.5: R64.2@64.554,9.75 64.579,9.75 65.469,10.64 65.758,10.64 67.233,12.114 Q2.3@70.811,12.114 70.811,12.149 71.029,12.367 71.064,12.367 71.357,12.66 C73.2@71.357,13.777 71.332,13.777 70.332,14.777 U12.1@70.332,18.435
  Bottom Layer w0.5: R88.2@65.705,9.75 65.774,9.819 65.774,10.682 pad.2@66.724,11.632
NetC78_2: C78.2 R7.2 R8.2 U3.5 | length 9
  Top Layer w0.254: R8.2@21.537,67.53 C78.2@21.537,69.472 ; C78.2@21.552,69.472 22.874,69.472 23.383,68.963 24.835,68.963 25.487,69.615 25.487,69.74 26.157,69.74 26.538,70.12 U3.5@27.799,70.12
NetC80_2: C80.2 R12.2 R66.2 U4.3 | length 7.8
  Top Layer w0.254: R66.2@16.182,48.844 16.118,48.78 16.118,48.151 16.513,47.756 17.055,47.756 17.707,47.104 R12.2@17.707,46.979 ; R12.2@17.707,46.979 18.264,46.979 19.261,45.981 20.217,45.981 U4.3@20.255,45.944
  Top Layer w0.5: R66.2@16.182,48.844 C80.2@16.182,50.785
NetC82_2: C82.2 R68.2 R69.2 R75.2 U4.5 | length 10
  Top Layer w0.254: R69.2@16.182,41.8 16.207,41.825 16.207,42.525 16.526,42.844 17.013,42.844 17.707,43.538 R68.2@17.707,43.663 ; R75.2@16.257,45.321 16.257,45.196 17.467,43.986 17.509,43.986 17.707,43.788 R68.2@17.707,43.663 ; U4.5@20.255,44.644 19.231,44.644 18.25,43.663 R68.2@17.707,43.663
  Top Layer w0.5: C82.2@16.182,39.858 R69.2@16.182,41.8
NetC91_2: C91.2 R80.2 R83.2 R84.2 U4.10 | length 8.7
  Top Layer w0.254: U4.10@26.155,44.644 26.192,44.606 27.118,44.606 27.663,44.061 R84.2@28.45,44.061 ; C91.2@28.45,42.12 R84.2@28.45,44.061 ; R80.2@29.975,47.583 29.975,47.458 29.777,47.26 29.736,47.26 28.525,46.05 R83.2@28.525,45.925 28.525,45.121 28.403,44.998 28.403,44.109 R84.2@28.45,44.061
NetC96_1: C96.1 U11.5 | length 1.5
  Top Layer w0.254: C96.1@46.984,8.788 47.151,8.621 U11.5@48.452,8.621
NetD1_1: D1.1 R2.2 | length 2.2
  Top Layer w0.5: D1.1@82.959,47.495 R2.2@85.15,47.495
NetD2_1: D2.1 R3.2 | length 11.8
  Top Layer w0.5: D2.1@78.742,47.481 79.708,47.481 80.001,47.188 80.001,46.895 81.05,45.845 87.41,45.845 89.035,47.47 R3.2@89.035,47.495
NetD3_1: D3.1 R5.2 | length 7
  Top Layer w0.5: D3.1@80.851,47.481 81.787,46.545 86.166,46.545 87.091,47.47 R5.2@87.091,47.495
NetD12_1: D12.1 D13.1 pad.2@25.305,13.265 pad.2@25.305,14.302 | length 3.9
  Bottom Layer w0.5: pad.2@25.305,13.265 25.332,13.265 25.789,13.723 25.91,13.723 ; pad.2@25.305,14.302 25.332,14.302 25.91,13.723 ; D13.1@28.154,13.723 25.91,13.723
NetJ1_1: J1.1 R1.1 | length 13.6
  Top Layer w0.5: J1.1@8.364,62.557 11.818,62.557 13.5,60.875 13.5,56.532 15.365,54.667 R1.1@16.182,54.667
NetJ2_1: J2.1 R4.1 | length 11
  Top Layer w0.5: J2.1@8.364,58.058 11.766,58.058 12.8,57.024 12.8,56.075 14.125,54.75 14.125,53.978 15.378,52.725 R4.1@16.182,52.725
NetJ6_3: J6.3 R18.2 | length 24.9
  Bottom Layer w0.254: R18.2@70.696,38.392 82.632,38.392 90.836,30.187 J6.3@90.836,28.798
NetJ7_3: J7.3 R17.2 | length 5.2
  Bottom Layer w0.254: J7.3@50.836,28.798 50.836,30.336 R17.2@53.434,32.934
NetJ10_3: J10.3 R16.2 | length 42.6
  Top Layer w0.254: J10.3@10.836,28.798 12.586,27.048 16.366,27.048 18.114,28.796 18.114,29.732 23.024,34.642 43.667,34.642 R16.2@47.434,38.409
NetJ15_1: J15.1 J15.9 pad.2@115,12.212 pad.2@115,21.902 R33.1 | length 29.3
  Top Layer w0.5: R33.1@103.305,17.948 104.689,17.948 105.38,18.639 111.26,18.639 114.524,21.902 pad.2@115,21.902 J15.1@117.366,21.902 ; pad.2@115,12.212 J15.9@117.366,12.212
  Bottom Layer w0.5: pad.2@115,12.212 115.63,12.212 115.944,12.526 115.944,21.588 115.649,21.883 115.019,21.883 pad.2@115,21.902
NetL1_3: L1.3 pad.2@97.619,12.477 pad.2@99.13,14.04 R37.1 U6.6 | length 8
  Top Layer w0.254: U6.6@96.451,12.477 pad.2@97.619,12.477 ; pad.2@99.13,14.04 L1.3@100.23,14.04
  Top Layer w0.5: L1.3@100.23,14.04 100.258,14.011 101.217,14.011 101.705,14.499 R37.1@101.705,15.829
  Bottom Layer w0.254: pad.2@97.619,12.477 98.558,12.477 99.13,13.049 pad.2@99.13,13.999
NetL1_4: L1.4 R34.1 U6.7 | length 7.5
  Top Layer w0.254: U6.7@96.451,13.127 98.418,13.127 100.005,11.54 L1.4@100.23,11.54
  Top Layer w0.5: L1.4@100.23,11.54 101.348,11.54 101.705,11.183 R34.1@101.705,9.75
NetQ1_1: Q1.1 R63.2 | length 1.8
  Top Layer w0.254: Q1.1@27.9,38.6 28.55,38.6 28.7,38.45 R63.2@29.625,38.45
NetQ2_1: Q2.1 R65.2 | length 5.2
  Top Layer w0.254: R65.2@66.83,10 R65.2@66.58,9.75 66.58,10.646 66.798,10.864 69.512,10.864 69.988,10.387 70.053,10.387 70.161,10.279 Q2.1@70.161,10.214
NetR6_1: pad.2@28.55,65.45 R6.1 U3.6 U3.7 | length 12.1
  Top Layer w0.254: U3.6@27.799,69.47 U3.7@27.799,68.82 27.799,67.159 28.55,66.408 pad.2@28.55,65.45
  Bottom Layer w0.254: pad.2@28.55,65.45 28.55,60.771 28.328,60.55 28.328,58.975 29.13,58.173 R6.1@29.13,58.148
NetR9_1: pad.2@18.938,43.369 pad.2@19.5,39.897 pad.2@20.255,47.844 R9.1 U4.1 U4.2 | length 54.3
  Top Layer w0.254: pad.2@18.938,43.369 18.938,43.341 19.231,43.047 19.231,40.711 19.434,40.508 19.434,39.964 pad.2@19.5,39.897 pad.2@19.566,39.964 ; U4.2@20.255,46.594 U4.1@20.255,47.244 pad.2@20.255,47.844
  Bottom Layer w0.254: pad.2@18.938,43.369 19.955,43.369 20.255,43.669 pad.2@20.255,47.844 ; pad.2@19.5,39.897 21.129,39.897 21.99,40.758 32.475,40.758 34.028,42.311 34.028,46.128 35.475,47.575 37.284,47.575 38.329,48.62 38.329,53.68 37.35,54.659 37.35,59.23 36.617,59.962 36.617,65.604 36.844,65.831 R9.1@36.844,66.73
NetR15_1: pad.2@32.602,69.163 R15.1 U3.8 U3.9 | length 7.4
  Top Layer w0.254: pad.2@32.602,69.163 32.631,69.163 32.936,68.858 33.661,68.858 U3.8@33.699,68.82 U3.9@33.699,69.47
  Bottom Layer w0.4: R15.1@27.349,68.604 31.989,68.604 32.548,69.163 pad.2@32.602,69.163
NetR26_2: R26.2 U5.8 | length 2.6
  Bottom Layer w0.254: U5.8@98.555,50.545 98.555,51.818 98.961,52.224 R26.2@98.961,52.949
NetR30_1: pad.2@27.799,73.44 R30.1 U3.1 U3.2 | length 19.5
  Top Layer w0.254: U3.2@27.799,72.07 U3.1@27.799,72.72 pad.2@27.799,73.44
  Bottom Layer w0.5: R30.1@21.779,59.328 21.779,65.729 23.379,67.329 23.379,69.021 24.098,69.74 26.76,69.74 27.799,70.779 pad.2@27.799,73.44
NetR31_1: pad.2@33.699,73.375 R31.1 U3.13 U3.14 | length 8
  Top Layer w0.254: U3.13@33.699,72.07 U3.14@33.699,72.72 pad.2@33.699,73.375
  Bottom Layer w0.5: R31.1@32.703,67.081 32.703,67.106 33.352,67.755 33.352,72.049 33.699,72.395 pad.2@33.699,73.375
NetR49_1: pad.2@25.454,8.146 R49.1 R58.2 U9.4 | length 9.8
  Top Layer w0.254: pad.2@25.454,8.146 U9.4@26.304,8.146
  Bottom Layer w0.254: R58.2@21.847,12.769 21.878,12.769 23.644,12.769 24.663,11.751 24.663,8.937 pad.2@25.454,8.146
  Bottom Layer w0.5: R58.2@21.878,12.769 21.953,12.844 21.953,14.353 R49.1@22.059,14.459
NetR50_1: R50.1 R53.2 U9.7 | length 3.9
  Top Layer w0.254: R50.1@27.381,2.64 R50.1@27.406,2.64 ; U9.7@27.904,4.346 27.904,3.163 27.754,3.013 27.754,2.988 R50.1@27.406,2.64 ; R53.2@29.386,2.64 R50.1@27.406,2.64
NetR50_2: R50.2 U9.6 | length 2.3
  Top Layer w0.254: R50.2@25.781,2.64 25.806,2.64 27.081,3.915 27.081,4.323 U9.6@27.104,4.346
NetR51_1: R51.1 U9.2 | length 1.8
  Top Layer w0.254: U9.2@27.904,8.146 27.904,8.784 28.15,9.031 28.15,9.735 R51.1@28.2,9.786
NetR54_2: R54.2 U10.4 | length 2.5
  Top Layer w0.5: R54.2@50.827,18.246 50.936,18.137 51.552,18.137 52.015,17.674 U10.4@53.11,17.674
